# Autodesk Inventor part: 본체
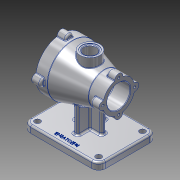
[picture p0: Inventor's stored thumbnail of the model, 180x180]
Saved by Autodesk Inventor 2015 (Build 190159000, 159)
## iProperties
Created: 2020-12
Part Number: 본체
Material: 알루미늄 6061
Document SubType Name: Modeling
Designer: Administrator
Density: 2.7 g/cm^3
Appearance: 알루미늄 - 평지
Mass: 1030.13 g
Surface Area: 850.653 cm^2
Volume: 381.528 cm^3
Author: Administrator
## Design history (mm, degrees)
sketch "스케치1"
  geometry: L1 (-65, 50)-(65, 50); L2 (65, 50)-(65, -50); L3 (65, -50)-(-65, -50); L4 (-65, -50)-(-65, 50); 3 further points
  constraints: 8 end point, 2 midpoint, 2 parallel, 1 horizontal, 1 horizontal alignment, 1 perpendicular, 1 vertical alignment
  dimensions: "d0" = 130 distance of L2.end L3.end; "d1" = 100 distance of L1.end L2.end
extrude "돌출1" new body sketch "스케치1" distance "d2" = 12; taper "d3" = 0 deg
sketch "스케치3"
  geometry: L1 (-65, 0)-(65, 0) reference; L2 (0, 0)-(0, 82); L3 (50, 82)-(-50, 82); L4 (50, 82)-(50, 126); L5 (50, 126)-(30, 126); L6 (-50, 82)-(-50, 109.5); L7 (-50, 109.5)-(-25, 109.5); L8 (-25, 109.5)-(30, 126)
  constraints: 14 end point, 3 vertical, 2 perpendicular, 1 horizontal, 1 midpoint
  dimensions: "d24" = 82 distance of L2.end L2.start; "d25" = 100 distance of L3.start L3.end; "d26" = 44 distance of L3.start L4.end; "d27" = 20 distance of L4.end L5.end; "d28" = 27.5 distance of L3.end L6.end; "d29" = 25 distance of L6.end L7.end
revolve "회전2" sketch "스케치3" stored, may be unused: angle "d30" = 90 deg
sketch "스케치4"
  geometry: L1 (50, 38)-(50, 126) reference; L2 (-50, 54.5)-(-50, 109.5) reference; L3 (50, 82)-(-50, 82); L4 (50, 82)-(50, 114); L5 (50, 114)-(27, 114); L6 (27, 114)-(27, 82); L7 (-50, 82)-(-50, 102); L8 (-50, 102)-(-20, 102); L9 (-20, 102)-(-20, 82); L10 (27, 108)-(-20, 108); L11 (-20, 102)-(-20, 108); 1 further point
  constraints: 18 end point, 5 perpendicular, 5 point on line, 2 midpoint, 1 horizontal
  dimensions: "d31" = 32 distance of L3.start L4.end; "d32" = 23 distance of L4.end L5.end; "d33" = 20 distance of L3.end L7.end; "d34" = 30 distance of L7.end L8.end; "d35" = 26 distance between parallel lines of L3 L10; "d36" = 47 distance between parallel lines of L9 L6 (derived)
revolve "회전3" sketch "스케치4" stored, may be unused: angle "d37" = 90 deg
fillet "모깎기1" dims "d38" = 3
chamfer "모따기1" distance "d39" = 1; stored, may be unused: second distance "d40" = 2, angle "d41" = 45 deg
sketch "스케치5"
  geometry: A1 r 7 centre (44, 0) between (43.443, -6.978) and (43.443, 6.978); A2 r 7 centre (0, 44) between (6.978, 43.443) and (-6.978, 43.443); A3 r 7 centre (-44, 0) between (-43.443, 6.978) and (-43.443, -6.978); A4 r 7 centre (0, -44) between (-6.978, -43.443) and (6.978, -43.443); 2 further points
  constraints: 8 point on circle, 4 centre point, 2 horizontal alignment, 2 vertical alignment, 13 other
  dimensions: "d42" = 7 radius of A1; "d43" = 7 radius of A2; "d44" = 7 radius of A3; "d45" = 7 radius of A4
extrude "돌출2" join sketch "스케치5" distance "d46" = 15; taper "d47" = 0 deg
sketch "스케치6"
  geometry: A1 r 7 centre (-27.5, 0) between (-26.609, 6.943) and (-26.609, -6.943); A2 r 7 centre (0, -27.5) between (-6.943, -26.609) and (6.943, -26.609); A3 r 7 centre (0, 27.5) between (6.943, 26.609) and (-6.943, 26.609); A4 r 7 centre (27.5, 0) between (26.609, -6.943) and (26.609, 6.943); 2 further points
  constraints: 8 point on circle, 4 centre point, 2 horizontal alignment, 2 vertical alignment, 13 other
  dimensions: "d48" = 7 radius of A1; "d49" = 7 radius of A2; "d50" = 7 radius of A3; "d51" = 7 radius of A4
extrude "돌출3" join sketch "스케치6" distance "d52" = 15; taper "d53" = 0 deg
sketch "스케치7"
  geometry: A1 r 7 centre (-55, 0) between (-54.109, 6.943) and (-54.109, -6.943) reference; A2 r 7 centre (-27.5, -27.5) between (-34.443, -26.609) and (-20.557, -26.609) reference; A3 r 7 centre (0, 0) between (-0.891, -6.943) and (-0.891, 6.943) reference; A4 r 7 centre (-27.5, 27.5) between (-20.557, 26.609) and (-34.443, 26.609) reference; 5 further points
  constraints: 4 coincident
hole "구멍1" sketch "스케치7" at (-55, 0), (-27.5, -27.5), (0, 0), (-27.5, 27.5) diameter "d54" = 4.134; stored, may be unused: countersink angle "d58" = 90 deg, drill point angle "d60" = 118 deg; dims "d55" = 9, "d56" = 4, "d57" = 2, "d59" = 11
sketch "스케치8"
  geometry: C1 r 33 at (44, 0) reference; A1 r 44 centre (44, 0) between (87.443, 6.978) and (50.978, 43.443) reference; A2 r 7 centre (44, 44) between (50.978, 43.443) and (37.022, 43.443) reference; A3 r 44 centre (44, 0) between (37.022, 43.443) and (0.557, 6.978) reference; A4 r 7 centre (0, 0) between (0.557, 6.978) and (0.557, -6.978) reference; A5 r 44 centre (44, 0) between (0.557, -6.978) and (37.022, -43.443) reference; A6 r 7 centre (44, -44) between (37.022, -43.443) and (50.978, -43.443) reference; A7 r 44 centre (44, 0) between (50.978, -43.443) and (87.443, -6.978) reference; A8 r 7 centre (88, 0) between (87.443, -6.978) and (87.443, 6.978) reference; 5 further points
  constraints: 4 coincident
hole "구멍2" sketch "스케치8" at (88, 0), (44, 44), (44, -44), (0, 0) diameter "d61" = 4.134; stored, may be unused: countersink angle "d65" = 90 deg, drill point angle "d67" = 118 deg; dims "d62" = 9, "d63" = 4, "d64" = 2, "d66" = 11
node "작업 평면1"
sketch "스케치9"
  geometry: C1 r 17 at (0, 0); 1 further point
  constraints: 1 centre point, 1 coincident
  dimensions: "d69" = 17 radius of C1
extrude "돌출4" join sketch "스케치9" stored distance "d70" = 15; taper "d71" = 0 deg
sketch "스케치10"
  geometry: C1 r 14 at (0, 0); 1 further point
  constraints: 1 centre point, 1 coincident
  dimensions: "d72" = 14 radius of C1
extrude "돌출5" cut sketch "스케치10" distance "d73" = 1; taper "d74" = 0 deg
sketch "스케치11"
  geometry: C1 r 11 at (0, 0); 1 further point
  constraints: 1 centre point, 1 coincident
  dimensions: "d75" = 11 radius of C1
extrude "돌출6" cut sketch "스케치11" distance "d76" = 32; taper "d77" = 0 deg
chamfer "모따기2" distance "d78" = 1; stored, may be unused: second distance "d79" = 2, angle "d80" = 45 deg
fillet "모깎기2" dims "d81" = 1
fillet "모깎기3" dims "d82" = 3
fillet "모깎기4" dims "d83" = 1
sketch "스케치12"
  geometry: L1 (65, 0)-(-65, 0) reference; L2 (-65, 12)-(65, 12) reference; L3 (24, 12)-(24, 45.511); L4 (-24, 12)-(-24, 55.931) reference; L5 (24, 12)-(-24, 12); L6 (-24, 55.931)-(24, 45.511) reference; 1 further point
  constraints: 8 end point, 2 point on line, 1 parallel, 1 vertical, 1 other
  dimensions: "d85" = 48 distance between parallel lines of L3 L4
extrude "돌출7" join sketch "스케치12" stored distance "d86" = 8; taper "d87" = 0 deg
sketch "스케치13"
  geometry: L1 (50, 12)-(-50, 12) reference; L2 (-25, 12)-(-25, 65.8); L3 (25, 12)-(25, 65.8) reference; L4 (-25, 12)-(25, 12); C1 r 26 at (0, 82) reference; A1 r 29.79 centre (0, 82) between (-25, 65.8) and (25, 65.8) reference; 1 further point
  constraints: 6 end point, 2 point on circle, 2 point on line, 1 centre point, 1 coincident, 1 parallel, 1 vertical, 1 other
  dimensions: "d89" = 50 distance between parallel lines of L2 L3
extrude "돌출8" join sketch "스케치13" stored distance "d90" = 8; taper "d91" = 0 deg
fillet "모깎기5" dims "d92" = 12
sketch "스케치14"
  geometry: C1 r 5 at (-53, 38); C2 r 5 at (53, 38); C3 r 5 at (-53, -38); C4 r 5 at (53, -38); A1 r 12 centre (-53, 38) between (-53, 50) and (-65, 38) reference; A2 r 12 centre (53, 38) between (65, 38) and (53, 50) reference; A3 r 12 centre (53, -38) between (53, -50) and (65, -38) reference; A4 r 12 centre (-53, -38) between (-65, -38) and (-53, -50) reference; 1 further point
  constraints: 4 centre point, 4 coincident
  dimensions: "d93" = 5 radius of C1; "d94" = 5 radius of C2; "d95" = 5 radius of C3; "d96" = 5 radius of C4
extrude "돌출9" cut sketch "스케치14" stored distance "d97" = 8; taper "d98" = 0 deg
fillet "모깎기6" dims "d99" = 3
fillet "모깎기8" dims "d101" = 3
fillet "모깎기9" dims "d102" = 3
sketch "스케치15"
  geometry: L1 (-53, -50)-(53, -50) reference; 2 further points
  constraints: 1 vertical alignment, 1 other
  dimensions: "d103" = 10 distance from line of L1 point (0, -40)
feature "엠보싱1" sketch "스케치15" dims "d0" = 130, "d1" = 100, "d104" = 0.5, "d105" = 0
fillet "모깎기10" dims "d106" = 3
node "솔리드1"
node "투영된 루프1"
other parameters: "d68" = 127
